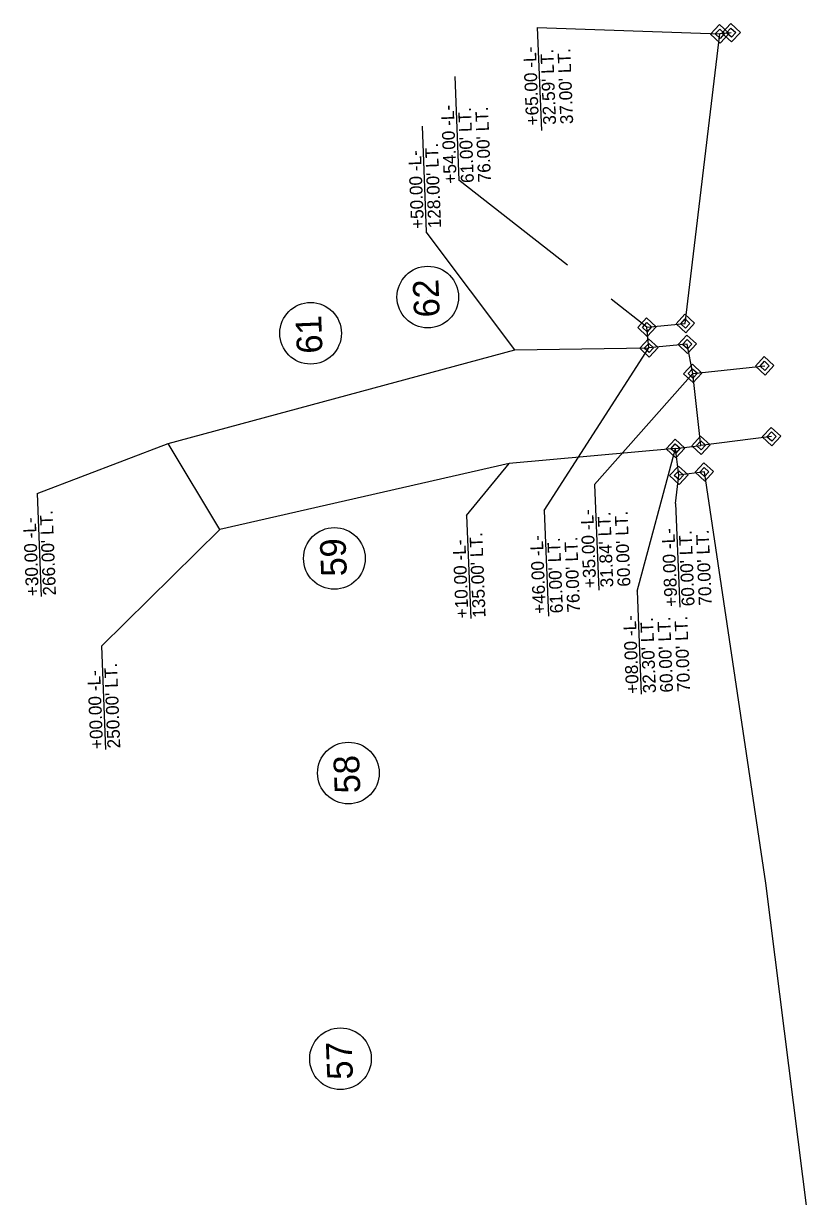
# Model space of a CAD drawing. Extents: x 1627970 to 1628801, y 761752 to 765698.
# Drawn here: x 1627970.2 to 1628275.5, y 765174.7 to 765631.2 of the extents above; entities that cross this region are included whole.
import ezdxf

# ---------------------------------------------------------------- set-up
doc = ezdxf.new("R2010")
doc.units = 0
for name, color, linetype in [('Exist Property Line Leader', 7, 'Continuous'), ('Exist Property Line Text', 7, 'Continuous'), ('Exist Property Owner Number CELL', 7, 'Continuous'), ('Exist Right of Way Monument Leader', 7, 'Continuous'), ('Exist Roads EOT', 7, 'Continuous'), ('Exist Utilities Other Unknown UG SUE Text', 7, 'Continuous'), ('Raster_Level_0', 7, 'Continuous'), ('Scratch_Level_2', 7, 'Continuous')]:
    doc.layers.add(name, color=color, linetype=linetype)

msp = doc.modelspace()

# ---------------------------------------------------------------- linework, layer by layer
at = {"layer": 'Exist Property Line Leader'}
for p, q in [((1628245.76, 765627.59), (1628241.37, 765627.17)), ((1628212.97, 765513), (1628227.9, 765514.41)), ((1628213.74, 765504.91), (1628212.97, 765513)), ((1628224.07, 765465.79), (1628234, 765467.02)), ((1628225.41, 765455.36), (1628224.07, 765465.79)), ((1628235.32, 765456.66), (1628225.41, 765455.36))]:
    msp.add_line(p, q, dxfattribs=at)
for points in [[(1628227.9, 765514.41), (1628241.37, 765627.17)], [(1628228.67, 765506.35), (1628213.74, 765504.91)], [(1628230.8, 765495.02), (1628228.67, 765506.35)], [(1628275.51, 765168.16), (1628259.21, 765296.59), (1628235.32, 765456.66)]]:
    msp.add_lwpolyline(points, dxfattribs=at)
at = {"layer": 'Exist Property Line Text'}
for p, q in [((1628127.63, 765524.72), (1628127.63, 765524.72)), ((1628081.99, 765510.62), (1628081.99, 765510.62)), ((1628091.25, 765423.01), (1628091.25, 765423.01)), ((1628096.71, 765339.51), (1628096.71, 765339.51)), ((1628093.63, 765228.32), (1628093.63, 765228.32))]:
    msp.add_line(p, q, dxfattribs=at)
for centre in [(1628127.63, 765524.72), (1628081.99, 765510.62), (1628091.25, 765423.01), (1628096.71, 765339.51), (1628093.63, 765228.32)]:
    msp.add_circle(centre, 12, dxfattribs=at)
at = {"layer": 'Exist Property Owner Number CELL'}
for p, q in [((1628230.8, 765495.02), (1628258.81, 765497.93)), ((1628234, 765467.02), (1628230.8, 765495.02)), ((1628261.48, 765470.43), (1628234, 765467.02))]:
    msp.add_line(p, q, dxfattribs=at)
at = {"layer": 'Exist Right of Way Monument Leader'}
for points in [[(1628237.77, 765627.03), (1628241.23, 765630.77), (1628244.97, 765627.31), (1628241.51, 765623.57)], [(1628242.16, 765627.44), (1628245.62, 765631.18), (1628249.36, 765627.73), (1628245.9, 765623.99)], [(1628239.57, 765627.1), (1628241.3, 765628.97), (1628243.17, 765627.24), (1628241.44, 765625.37)], [(1628243.96, 765627.51), (1628245.69, 765629.38), (1628247.56, 765627.66), (1628245.83, 765625.79)], [(1628209.37, 765512.86), (1628212.83, 765516.59), (1628216.57, 765513.14), (1628213.11, 765509.4)], [(1628224.31, 765514.26), (1628227.76, 765518), (1628231.5, 765514.55), (1628228.05, 765510.81)], [(1628211.17, 765512.93), (1628212.9, 765514.8), (1628214.77, 765513.07), (1628213.04, 765511.2)], [(1628226.11, 765514.34), (1628227.83, 765516.21), (1628229.7, 765514.48), (1628227.98, 765512.61)], [(1628210.14, 765504.77), (1628213.59, 765508.51), (1628217.33, 765505.06), (1628213.88, 765501.32)], [(1628225.07, 765506.2), (1628228.53, 765509.94), (1628232.26, 765506.49), (1628228.81, 765502.75)], [(1628226.87, 765506.28), (1628228.6, 765508.14), (1628230.46, 765506.42), (1628228.74, 765504.55)], [(1628211.94, 765504.84), (1628213.66, 765506.71), (1628215.53, 765504.98), (1628213.81, 765503.11)], [(1628227.21, 765494.88), (1628230.66, 765498.61), (1628234.4, 765495.16), (1628230.95, 765491.42)], [(1628255.21, 765497.79), (1628258.67, 765501.53), (1628262.41, 765498.07), (1628258.95, 765494.33)], [(1628257.01, 765497.86), (1628258.74, 765499.73), (1628260.61, 765498), (1628258.88, 765496.13)], [(1628229.01, 765494.95), (1628230.73, 765496.82), (1628232.6, 765495.09), (1628230.88, 765493.22)], [(1628257.89, 765470.28), (1628261.34, 765474.02), (1628265.08, 765470.57), (1628261.63, 765466.83)], [(1628259.69, 765470.36), (1628261.41, 765472.22), (1628263.28, 765470.5), (1628261.56, 765468.63)], [(1628220.48, 765465.64), (1628223.93, 765469.38), (1628227.67, 765465.93), (1628224.22, 765462.19)], [(1628222.28, 765465.71), (1628224, 765467.58), (1628225.87, 765465.86), (1628224.15, 765463.99)], [(1628230.4, 765466.87), (1628233.86, 765470.61), (1628237.59, 765467.16), (1628234.14, 765463.42)], [(1628232.2, 765466.95), (1628233.93, 765468.82), (1628235.8, 765467.09), (1628234.07, 765465.22)], [(1628221.81, 765455.22), (1628225.26, 765458.96), (1628229, 765455.5), (1628225.55, 765451.76)], [(1628231.72, 765456.52), (1628235.18, 765460.26), (1628238.92, 765456.8), (1628235.46, 765453.07)], [(1628233.52, 765456.59), (1628235.25, 765458.46), (1628237.12, 765456.73), (1628235.39, 765454.86)], [(1628223.61, 765455.29), (1628225.34, 765457.16), (1628227.2, 765455.43), (1628225.48, 765453.56)]]:
    msp.add_lwpolyline(points, close=True, dxfattribs=at)
at = {"layer": 'Exist Roads EOT'}
for p, q in [((1628170.27, 765629.62), (1628171.86, 765589.48)), ((1628170.27, 765629.62), (1628241.37, 765627.17)), ((1628138.16, 765610.59), (1628139.76, 765570.18)), ((1628182.04, 765537.15), (1628139.76, 765570.18)), ((1628212.97, 765513), (1628199, 765523.91)), ((1628172.96, 765441.68), (1628213.74, 765504.91)), ((1628192.57, 765451.78), (1628230.8, 765495.02)), ((1628209.1, 765410.31), (1628224.07, 765465.79)), ((1628224.12, 765444.45), (1628225.41, 765455.36)), ((1628192.57, 765451.78), (1628194.2, 765410.62)), ((1628224.12, 765444.45), (1628225.71, 765404.03)), ((1628172.96, 765441.68), (1628174.59, 765400.52)), ((1628209.1, 765410.31), (1628210.68, 765370.18))]:
    msp.add_line(p, q, dxfattribs=at)
at = {"layer": 'Exist Utilities Other Unknown UG SUE Text'}
for p, q in [((1628241.37, 765627.17), (1628241.37, 765627.17)), ((1628245.76, 765627.59), (1628245.76, 765627.59)), ((1628212.97, 765513), (1628212.97, 765513)), ((1628227.9, 765514.41), (1628227.9, 765514.41)), ((1628213.74, 765504.91), (1628213.74, 765504.91)), ((1628228.67, 765506.35), (1628228.67, 765506.35)), ((1628230.8, 765495.02), (1628230.8, 765495.02)), ((1628258.81, 765497.93), (1628258.81, 765497.93)), ((1628234, 765467.02), (1628234, 765467.02)), ((1628261.48, 765470.43), (1628261.48, 765470.43)), ((1628224.07, 765465.79), (1628224.07, 765465.79)), ((1628225.41, 765455.36), (1628225.41, 765455.36)), ((1628235.32, 765456.66), (1628235.32, 765456.66))]:
    msp.add_line(p, q, dxfattribs=at)
at = {"layer": 'Raster_Level_0'}
for p, q in [((1628125.43, 765591.24), (1628127.05, 765550.16)), ((1628161.58, 765504.13), (1628127.05, 765550.16)), ((1627975.46, 765448.33), (1628026.54, 765467.75)), ((1628142.75, 765439.71), (1628159.3, 765459.96)), ((1627975.46, 765448.33), (1627977.04, 765408.19)), ((1628142.75, 765439.71), (1628144.33, 765399.58)), ((1628000.51, 765388.86), (1628046.64, 765434.24)), ((1628000.51, 765388.86), (1628002.09, 765348.72))]:
    msp.add_line(p, q, dxfattribs=at)
at = {"layer": 'Scratch_Level_2'}
for p, q in [((1628026.54, 765467.75), (1628161.58, 765504.13)), ((1628161.58, 765504.13), (1628213.74, 765504.91)), ((1628046.64, 765434.24), (1628026.54, 765467.75)), ((1628224.07, 765465.79), (1628159.3, 765459.96)), ((1628159.3, 765459.96), (1628046.64, 765434.24))]:
    msp.add_line(p, q, dxfattribs=at)

# ---------------------------------------------------------------- texts
at = {"layer": 'Exist Property Line Text'}
for s, p in [('62', (1628132.31, 765516.99)), ('61', (1628086.67, 765502.89)), ('59', (1628096.14, 765416.18)), ('58', (1628101.4, 765331.78)), ('57', (1628098.52, 765220.36))]:
    msp.add_text(s, height=10, rotation=92.2582, dxfattribs=at).set_placement(p)
at = {"layer": 'Exist Roads EOT'}
for s, p in [('+65.00 -L-', (1628170.93, 765591.57)), ("32.59' LT.", (1628177.6, 765591.84)), ("37.00' LT.", (1628184.26, 765592.1)), ('+54.00 -L-', (1628138.92, 765568.93)), ("61.00' LT.", (1628145.58, 765569.19)), ("76.00' LT.", (1628152.24, 765569.45)), ('+35.00 -L-', (1628193.24, 765411.59)), ("31.84' LT.", (1628199.9, 765411.85)), ("60.00' LT.", (1628206.56, 765412.11)), ('+98.00 -L-', (1628224.87, 765404.24)), ('+46.00 -L-', (1628173.62, 765401.49)), ("61.00' LT.", (1628180.29, 765401.75)), ("76.00' LT.", (1628186.95, 765402.02)), ("60.00' LT.", (1628231.53, 765404.5)), ("70.00' LT.", (1628238.19, 765404.76)), ('+08.00 -L-', (1628209.84, 765370.38)), ("32.30' LT.", (1628216.5, 765370.65)), ("60.00' LT.", (1628223.16, 765370.91)), ("70.00' LT.", (1628229.82, 765371.17))]:
    msp.add_text(s, height=5, rotation=92.2582, dxfattribs=at).set_placement(p)
at = {"layer": 'Raster_Level_0'}
for s, p in [('+50.00 -L-', (1628126.17, 765551.31)), ("128.00' LT.", (1628132.83, 765551.57)), ("266.00' LT.", (1627982.85, 765408.66)), ('+30.00 -L-', (1627976.19, 765408.4)), ('+10.00 -L-', (1628143.48, 765399.79)), ("135.00' LT.", (1628150.15, 765400.05)), ("250.00' LT.", (1628007.9, 765349.2)), ('+00.00 -L-', (1628001.24, 765348.93))]:
    msp.add_text(s, height=5, rotation=92.2582, dxfattribs=at).set_placement(p)

doc.saveas('drawing.dxf')
